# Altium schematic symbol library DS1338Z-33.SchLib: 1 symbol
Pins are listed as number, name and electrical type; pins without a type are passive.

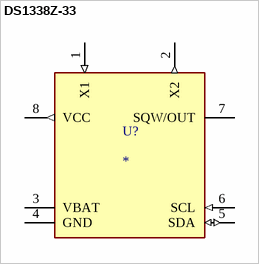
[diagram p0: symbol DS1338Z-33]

## DS1338Z-33
designator U?
Real Time Clock (RTC) IC Clock/Calendar 56B IÂ²C, 2-Wire Serial 8-SOIC (0.154, 3.90mm Width); MP: DS1338Z-33+; MF: Maxim Integrated
footprint DS1338Z-33
pins: 1 X1 (in), 2 X2 (out), 3 VBAT (power), 4 GND (power), 5 SDA (io), 6 SCL (in), 7 SQW/OUT (power), 8 VCC (out)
